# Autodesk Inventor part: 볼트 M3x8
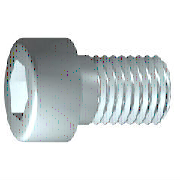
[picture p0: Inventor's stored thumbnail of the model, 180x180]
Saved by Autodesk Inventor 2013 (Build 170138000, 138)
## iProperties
IsCustomPart: 0
Created: 2012-02
Part Number: 볼트 M3x8
Material: 강철, 연강
Description: 6각머리 태핑 나사
Document SubType Name: Modeling
Standard: KS B 1003
Designer: mduedu
Standards Organization: KS
Language: ko-KR
Size Designation: M 3 x 8
Categories: <MemberInstance><Categories><Category DisplayName="조임쇠" InternalName="e4da775c-781d-43d5-af7c-5136215cf5a6" Mnemonic="FSTN"><Category DisplayName="볼트" InternalN
Density: 1 g/cm^3
Author: mduedu
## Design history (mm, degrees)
sketch "스케치1"
  geometry: L1 (-0.867, 0)-(8, 0); L2 (8, 0)-(8, 1.5); L3 (8, 1.5)-(1.25, 1.5); L4 (1.25, 1.5)-(0.943, 1.5); L5 (0.943, 1.5)-(0, 1.5); L6 (0, 1.5)-(0, 2.75); L7 (0, 2.75)-(-3, 2.75); L8 (-3, 2.75)-(-3, 1.443); L9 (-3, 1.443)-(-1.7, 1.443); L10 (-1.7, 1.443)-(-0.867, 0); L11 (-5.2, 0)-(10.2, 0) reference; L12 (0, -0.55)-(0, 3.3) reference; L13 (1.25, 1.5)-(0, 1.5)
  constraints: 22 end point, 6 parallel, 2 collinear, 2 perpendicular, 1 horizontal, 1 point on line
  dimensions: "d1" = 6.75 distance from line of L3.end L2 (= GEL); "d2" = 0.30683 distance of L4.end L3.end (computed from GAL); "d3" = 3 distance between parallel lines of L8 L6 (= KOH); "d4" = 1.3 distance of L8.end L9.end (= INTI); "d5" = 60 deg angle of L10 L1; "d6" = 3 diameter of L3 L1 (= GD); "d7" = 3 diameter of L5 L1 (= BDM); "d8" = 2.88675 diameter of L9 L1 (= 1.1547 x SW); "d9" = 5.5 diameter of L7 L1 (= KOD); "d26" = 8 distance between parallel lines of L12 L2 (= NLG)
revolve "본체" sketch "스케치1" stored, may be unused: angle "d10" = 90 deg
sketch "스케치2"
  geometry: L1 (0, -3.85)-(0, 3.85) reference; L2 (-3.85, 0)-(3.85, 0) reference; L3 (1.443, 0)-(0.722, -1.25); L4 (0.722, -1.25)-(-0.722, -1.25); L5 (-0.722, -1.25)-(-1.443, 0); L6 (-1.443, 0)-(-0.722, 1.25); L7 (-0.722, 1.25)-(0.722, 1.25); L8 (0.722, 1.25)-(1.443, 0); 2 further points
  constraints: 12 end point, 1 coincident, 1 horizontal alignment, 1 point on line, 12 other
extrude "슬롯" join sketch "스케치2" stored distance "d11" = 10; taper "d12" = 0 deg
workplane "Work Plane1"
fillet "Fillet2" dims "d30" = 0.1 (= R)
body "Solid1"
fillet "모깎기1" dims "d17" = 0.3 (= RR)
feature "스레드" dims "d13" = 6.75 (= GEL), "d14" = 0
chamfer "모따기1" distance "d15" = 0.30673 (= -0.5 x SPD + 0.5 x GD); stored, may be unused: second distance "d16" = 0.30673 (= GUL), angle "d27" = 45 deg
other parameters: "GD" = 3 (= NND) [user parameter; used in 2 equation terms], "NLG" = 8 [user parameter; used in 1 equation term], "GEL" = 6.75 [user parameter; used in 2 equation terms], "KOD" = 5.5 [user parameter; used in 1 equation term], "KOH" = 3 [user parameter; used in 1 equation term], "INTI" = 1.3 [user parameter; used in 1 equation term], "GAL" = 0.30673 (= 0.61345 x PTC) [user parameter; used in 1 equation term], "GUL" = 0.30673 (= 0.61345 x PTC) [user parameter; used in 1 equation term], "BDM" = 3 (= NND) [user parameter; used in 1 equation term], "SW" = 2.5 [user parameter; used in 2 equation terms], "RR" = 0.3 [user parameter; used in 1 equation term], "SPD" = 2.38655 (= NND - 1.2269 x PTC) [user parameter; used in 1 equation term], "d19" = 0, "d28" = 0, "d29" = 0, "R" = 0.1 [user parameter; used in 1 equation term], "PHH" = 0.1 [user parameter], "GD1" = 2.38655 (= THREADDIA - 1.2269 x PTC) [user parameter], "THREADDIA" = 3 [user parameter; used in 1 equation term], "FAWI" = 45 deg [user parameter], "PTC" = 0.5 [user parameter; used in 5 equation terms], "NND" = 3 [user parameter; used in 3 equation terms], "TOA" = 30 deg [user parameter], "E0" = 2.8875 (= 1.155 x SW) [user parameter]
